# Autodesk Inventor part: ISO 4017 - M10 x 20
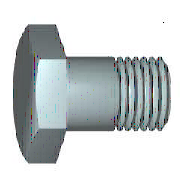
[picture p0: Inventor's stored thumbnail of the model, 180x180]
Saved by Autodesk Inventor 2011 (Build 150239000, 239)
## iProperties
IsCustomPart: 0
Created: 2009-02
Part Number: ISO 4017 - M10 x 20
Material: Stainless Steel, 440C
Description: Hexagon head screws
Document SubType Name: Modeling
Standard: ISO 4017
Designer: 904Chiaki
Standard Revision: Third edition 1999-08-15
Standards Organization: ISO
Language: en-US
Size Designation: M10 x 20
Categories: <MemberInstance><Categories><Category DisplayName="Fasteners" InternalName="e4da775c-781d-43d5-af7c-5136215cf5a6" Mnemonic="FSTN"><Category DisplayName="Bolts"
Density: 7.75 g/cm^3
Author: 904Chiaki
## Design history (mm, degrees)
body "Solid1"
workplane "Work Plane1"
revolve "Body" stored, may be unused: angle "d12" = 90 deg
sketch "Sketch2"
  geometry: L1 (0, 9.238)-(8, 4.619); L2 (8, 4.619)-(8, -4.619); L3 (8, -4.619)-(0, -9.238); L4 (0, -9.238)-(-8, -4.619); L5 (-8, -4.619)-(-8, 4.619); L6 (-8, 4.619)-(0, 9.238); 2 further points
  constraints: 12 end point, 1 coincident, 1 vertical, 11 other
  dimensions: "d11" = 16 distance between parallel lines of L5 L2 (= SW)
extrude "Head" join sketch "Sketch2" distance "d3" = 5.8 (= KOH - SD); taper "d4" = 0 deg
revolve "Chamfer1" stored, may be unused: angle "d21" = 90 deg
feature "Thread" dims "d15" = 15.5 (= GEL), "d16" = 0
chamfer "Chamfer2" distance "d6" = 0.92018 (= -0.5 x SPD + 0.5 x GD); stored, may be unused: second distance "d7" = 0.92028 (computed from GUL), angle "d55" = 45 deg
sketch "Sketch1"
  geometry: L1 (0, 7.315)-(0, 5); L2 (4.5, 5)-(20, 5); L3 (20, 5)-(20, 0); L4 (20, 0)-(-0.6, 0); L5 (-4.72, 0)-(24.12, 0) reference; L6 (-0.6, 0)-(-0.6, 7.315); L7 (-0.6, 7.315)-(0, 7.315); L8 (4.5, 5)-(3.58, 5); L9 (3.58, 5)-(0, 5); L10 (0, -1.463)-(0, 8.778) reference
  constraints: 16 end point, 2 collinear, 2 perpendicular, 1 parallel
  dimensions: "d0" = 20 distance between parallel lines of L3 L1 (= NLG); "d1" = 15.5 distance from line of L2.start L3 (= GEL); "d2" = 10 diameter of L2 L4 (= GD); "d9" = 0.6001 distance between parallel lines of L6 L1 (computed from SD); "d10" = 14.63 diameter of L7 L4 (= SD2); "d13" = 0.92028 distance of L2.start L8.end (computed from GAL); "d14" = 10 diameter of L9 L4 (= BDM)
sketch "Sketch4"
  geometry: L1 (-6.4, 8)-(-6.4, 9.238); L2 (-6.4, 9.238)-(-5.686, 9.238); L3 (-5.686, 9.238)-(-6.4, 8); L4 (-7.56, 0)-(0.56, 0) reference; L5 (-0.6, 9.238)-(-6.4, 9.238) reference; L6 (-6.4, 4.619)-(-6.4, 9.238) reference
  constraints: 6 end point, 2 collinear, 1 perpendicular, 1 vertical
  dimensions: "d5" = 30 deg angle of L3 L1 (= ANG1); "d19" = 16 diameter of L1.start L4 (= SW0)
other parameters: "NLG" = 20 [user parameter; used in 1 equation term], "GD" = 10 (= NND) [user parameter; used in 2 equation terms], "BDM" = 10 (= NND) [user parameter; used in 1 equation term], "KOH" = 6.4 [user parameter; used in 1 equation term], "GEL" = 15.5 [user parameter; used in 2 equation terms], "SW" = 16 [user parameter; used in 2 equation terms], "SW0" = 16 (= SW) [user parameter; used in 1 equation term], "SPD" = 8.15965 (= NND - 1.2269 x PTC) [user parameter; used in 1 equation term], "SD2" = 14.63 [user parameter; used in 2 equation terms], "SD" = 0.6 [user parameter; used in 2 equation terms], "ANG1" = 30 deg [user parameter; used in 1 equation term], "GAL" = 0.92018 (= 0.61345 x PTC) [user parameter; used in 1 equation term], "GUL" = 0.92018 (= 0.61345 x PTC) [user parameter; used in 1 equation term], "d8" = 0, "RR" = 0.4 [user parameter], "d57" = 0, "d58" = 0, "TPU" = 6.66667 (computed from PTC) [user parameter], "GD1" = 8.15965 (= THREADDIA - 1.2269 x PTC) [user parameter], "SDH" = 14.63 (= SD2) [user parameter], "SDHG" = 4.5 [user parameter], "TOA" = 30 deg [user parameter], "PTC" = 1.5 [user parameter; used in 5 equation terms], "E0" = 18.48 [user parameter]
